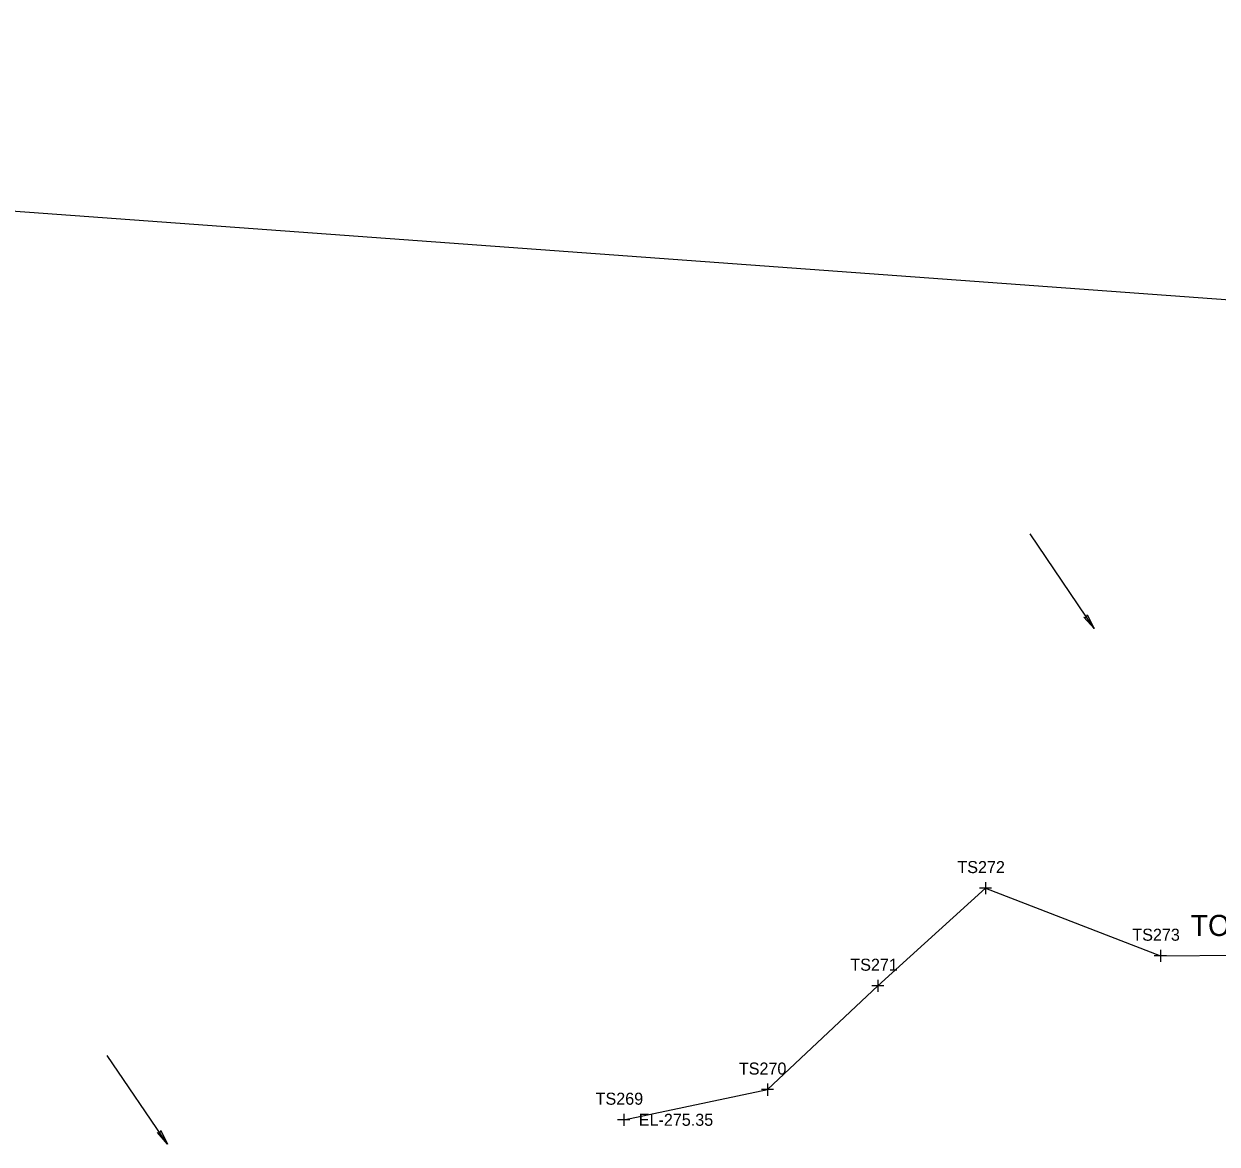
# Model space of a CAD drawing. Extents: x 818717 to 846077, y 440014 to 541392.
# Drawn here: x 830937.7 to 831333.4, y 493359.1 to 493730.8 of the extents above; entities that cross this region are included whole.
import ezdxf

# ---------------------------------------------------------------- set-up
doc = ezdxf.new("R2010")
doc.units = 0
for name, color, linetype in [('SURVEY - DRAINAGE - Natural Features Text', 7, 'Continuous'), ('SURVEY - DTM - Breaklines', 7, 'Continuous'), ('SURVEY - DTM - Breaklines - Points - Elevations', 7, 'Continuous'), ('SURVEY - DTM - Breaklines - Points - Locators', 7, 'Continuous'), ('SURVEY - DTM - Breaklines - Points - Numbers', 7, 'Continuous'), ('SURVEY - PROPERTY - Property Lines', 7, 'Continuous')]:
    doc.layers.add(name, color=color, linetype=linetype)

msp = doc.modelspace()

# ---------------------------------------------------------------- linework, layer by layer
at = {"layer": 'SURVEY - DRAINAGE - Natural Features Text'}
for p, q in [((831292.61, 493530.18), (831271.43, 493561.57)), ((831291.1, 493532.42), (831292.61, 493530.18)), ((830985.36, 493359.1), (830965.36, 493388.47)), ((830983.86, 493361.35), (830985.36, 493359.1))]:
    msp.add_line(p, q, dxfattribs=at)
for points in [[(831292.61, 493530.18), (831289.24, 493534), (831290.15, 493533.83), (831290.32, 493534.73)], [(830985.36, 493359.1), (830982.01, 493362.94), (830982.92, 493362.76), (830983.1, 493363.67)]]:
    msp.add_lwpolyline(points, close=True, dxfattribs=at)
for points in [[(831292.61, 493530.18), (831289.24, 493534), (831290.15, 493533.83), (831290.32, 493534.73), (831292.61, 493530.18)], [(830985.36, 493359.1), (830982.01, 493362.94), (830982.92, 493362.76), (830983.1, 493363.67), (830985.36, 493359.1)]]:
    msp.add_lwpolyline(points, dxfattribs=at)
at = {"layer": 'SURVEY - DTM - Breaklines'}
msp.add_lwpolyline([(831136.62, 493367.18), (831184.28, 493377.18), (831220.92, 493411.64), (831256.58, 493444.04), (831314.6, 493421.59), (831366.62, 493422.03), (831418.68, 493418.44), (831473.18, 493423.8), (831520.74, 493443.82), (831571.47, 493443.97), (831625.9, 493448.49)], dxfattribs=at)
at = {"layer": 'SURVEY - DTM - Breaklines - Points - Locators'}
for p, q in [((831256.58, 493446.04), (831256.58, 493442.04)), ((831258.58, 493444.04), (831254.58, 493444.04)), ((831316.6, 493421.59), (831312.6, 493421.59)), ((831314.6, 493423.59), (831314.6, 493419.59)), ((831220.92, 493413.64), (831220.92, 493409.64)), ((831222.92, 493411.64), (831218.92, 493411.64)), ((831186.28, 493377.18), (831182.28, 493377.18)), ((831184.28, 493379.18), (831184.28, 493375.18)), ((831136.62, 493369.18), (831136.62, 493365.18)), ((831138.62, 493367.18), (831134.62, 493367.18))]:
    msp.add_line(p, q, dxfattribs=at)
at = {"layer": 'SURVEY - PROPERTY - Property Lines'}
msp.add_line((830086.25, 493730.81), (831750.35, 493609), dxfattribs=at)

# ---------------------------------------------------------------- texts
at = {"layer": 'SURVEY - DTM - Breaklines'}
msp.add_text('TOE OF SLOPE', height=7, dxfattribs=at).set_placement((831324.71, 493428.17))
at = {"layer": 'SURVEY - DTM - Breaklines - Points - Elevations'}
msp.add_text('EL-275.35', height=4, dxfattribs=at).set_placement((831141.62, 493365.18))
at = {"layer": 'SURVEY - DTM - Breaklines - Points - Numbers'}
for s, p in [('TS272', (831247.29, 493449.04)), ('TS273', (831305.31, 493426.59)), ('TS271', (831211.79, 493416.64)), ('TS270', (831174.82, 493382.18)), ('TS269', (831127.32, 493372.18))]:
    msp.add_text(s, height=4, dxfattribs=at).set_placement(p)

doc.saveas('drawing.dxf')
